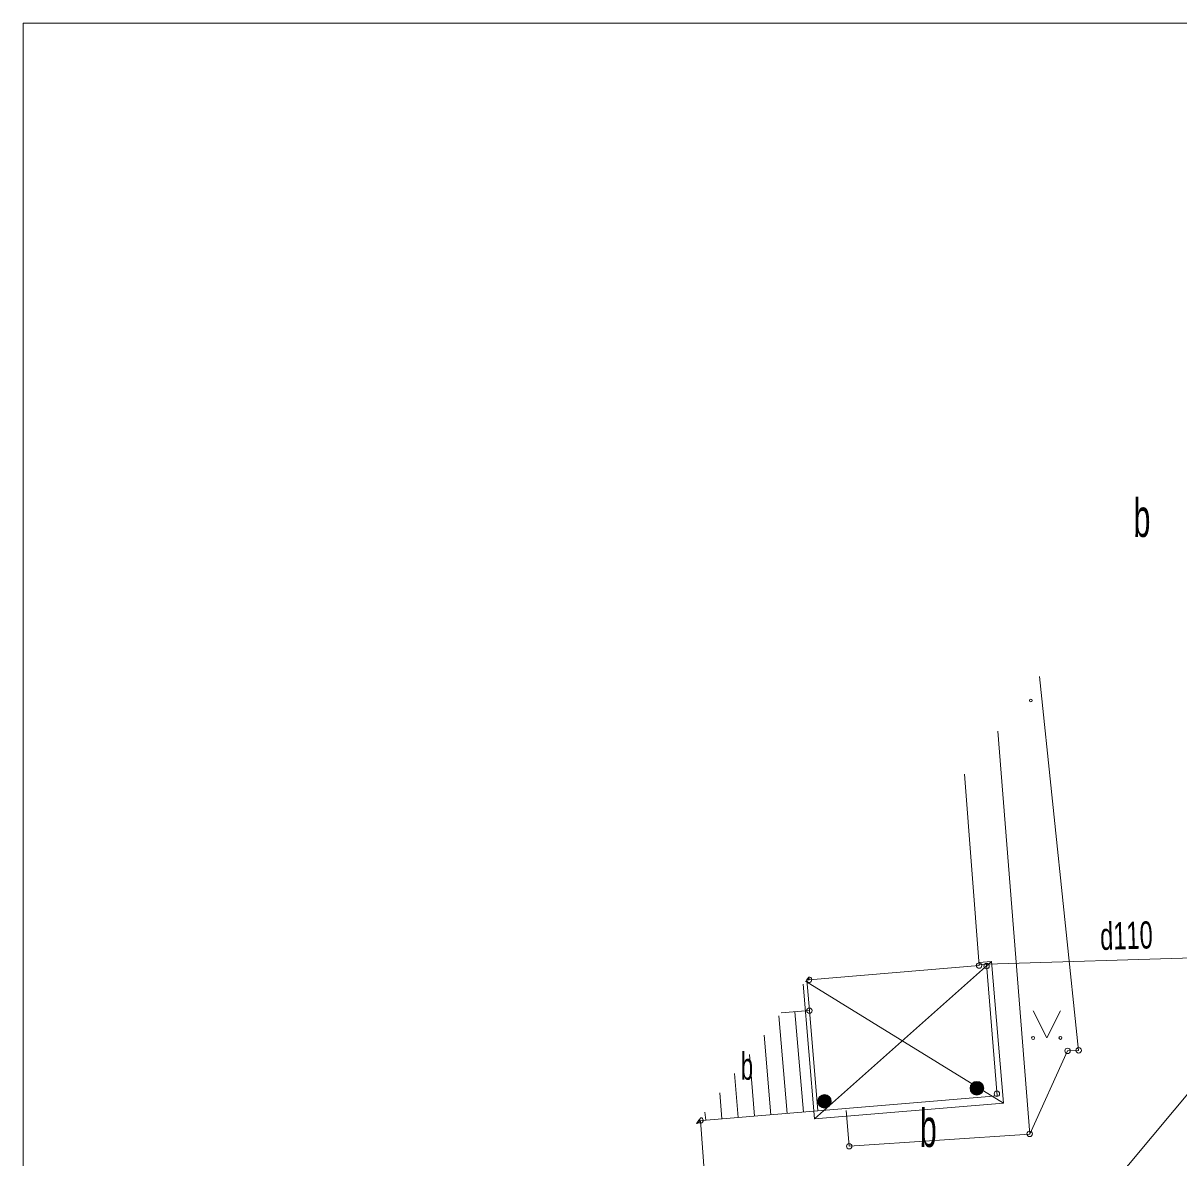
# Model space of a CAD drawing. Extents: x -1271.1 to -1218.8, y 769 to 838.3.
# Drawn here: x -1268.85 to -1247.62, y 817.43 to 838.28 of the extents above; entities that cross this region are included whole.
import ezdxf
from ezdxf.enums import TextEntityAlignment as Align

# ---------------------------------------------------------------- set-up
doc = ezdxf.new("R2010")
doc.units = 0
doc.header["$LTSCALE"] = 0.2
for name, color, linetype, lineweight in [('1', 7, 'Continuous', 13), ('19', 7, 'Continuous', 13), ('3', 7, 'Continuous', 13), ('5', 7, 'Continuous', 13), ('56', 7, 'Continuous', 13), ('59', 7, 'Continuous', 13), ('6', 7, 'Continuous', 13), ('60', 7, 'Continuous', 13), ('63', 7, 'Continuous', 13), ('7', 7, 'Continuous', 13)]:
    doc.layers.add(name, color=color, linetype=linetype, lineweight=lineweight)
for name, color, linetype in [('10', 7, 'Continuous'), ('11', 7, 'Continuous'), ('15', 7, 'Continuous')]:
    doc.layers.add(name, color=color, linetype=linetype)

msp = doc.modelspace()

# ---------------------------------------------------------------- hatches: boundary and pattern name
at = {"layer": '7'}
for points in [[(-1251.21, 818.7142, 1), (-1251.46, 818.7142, 1)], [(-1254.01, 818.4732, 1), (-1254.26, 818.4732, 1)]]:
    msp.add_hatch(color=256, dxfattribs=at).paths.add_polyline_path(points)

# ---------------------------------------------------------------- linework, layer by layer
at = {"layer": '1'}
msp.add_spline([(-1235.8, 825.801), (-1237.913, 825.174), (-1239.203, 823.346), (-1241.709, 821.268), (-1246.557, 815.58), (-1256.526, 805.053), (-1260.592, 799.147), (-1261.416, 795.29), (-1262.742, 791.444), (-1262.206, 785.139)], degree=3, dxfattribs=at)
at = {"layer": '19'}
msp.add_spline([(-1253.457, 785.393), (-1253.726, 794.104), (-1251.637, 801.373), (-1250.122, 804.26), (-1247.608, 807.348), (-1239.437, 815.545), (-1236.508, 819.221), (-1228.799, 821.851), (-1223.357, 826.161), (-1220.079, 827.95)], degree=3, dxfattribs=at)
at = {"layer": '3'}
msp.add_line((-1251.16, 820.99), (-1241.778, 821.284), dxfattribs=at)
at = {"layer": '5'}
msp.add_lwpolyline([(-1250.301, 820.138), (-1250.051, 819.638), (-1249.801, 820.138)], dxfattribs=at)
for centre, radius in [((-1250.345, 825.8366), 0.0263), ((-1250.3016, 819.6377), 0.028), ((-1249.8016, 819.6377), 0.0263)]:
    msp.add_circle(centre, radius, dxfattribs=at)
at = {"layer": '56'}
for p, q in [((-1251.294, 820.98), (-1251.16, 820.99)), ((-1251.16, 820.99), (-1250.965, 818.572)), ((-1254.418, 820.706), (-1254.458, 820.703)), ((-1254.458, 820.703), (-1254.411, 820.139)), ((-1254.93, 820.096), (-1254.411, 820.139)), ((-1254.676, 820.117), (-1254.522, 818.275)), ((-1254.411, 820.139), (-1254.257, 818.297)), ((-1254.971, 820.042), (-1254.821, 818.25)), ((-1255.242, 819.689), (-1255.12, 818.225)), ((-1255.514, 819.335), (-1255.419, 818.2)), ((-1255.786, 818.982), (-1255.718, 818.175)), ((-1256.057, 818.628), (-1256.017, 818.15)), ((-1256.452, 818.114), (-1250.965, 818.572)), ((-1256.329, 818.275), (-1256.316, 818.125))]:
    msp.add_line(p, q, dxfattribs=at)
at = {"layer": '59'}
for p, q in [((-1251.56, 824.483), (-1251.293, 820.967)), ((-1254.418, 820.706), (-1251.293, 820.967)), ((-1254.422, 820.757), (-1254.418, 820.706))]:
    msp.add_line(p, q, dxfattribs=at)
at = {"layer": '6'}
for p, q in [((-1254.423, 820.756), (-1254.467, 820.698)), ((-1256.431, 818.142), (-1256.487, 818.069)), ((-1256.407, 818.173), (-1256.459, 818.105))]:
    msp.add_line(p, q, dxfattribs=at)
for centre in [(-1251.293, 820.9672), (-1251.157, 820.9562), (-1254.411, 820.1392), (-1249.669, 819.3992), (-1249.466, 819.4092), (-1250.968, 818.6122), (-1250.365, 817.8762), (-1253.68, 817.6481)]:
    msp.add_circle(centre, 0.05, dxfattribs=at)
for centre, start, end in [((-1254.418, 820.7062), 189.39039, 95.55119), ((-1256.474, 818.1172), 255.07057, 29.871), ((-1256.412, 818.1232), 200.73646, 84.20513)]:
    msp.add_arc(centre, 0.05, start, end, dxfattribs=at)
at = {"layer": '60'}
for p, q in [((-1254.318, 818.152), (-1251.065, 821.041)), ((-1251.297, 821.023), (-1251.065, 821.041)), ((-1251.065, 821.041), (-1250.848, 818.442)), ((-1254.525, 820.623), (-1254.318, 818.152)), ((-1254.481, 820.681), (-1250.848, 818.442)), ((-1254.419, 820.721), (-1254.452, 820.719)), ((-1254.318, 818.152), (-1250.848, 818.442))]:
    msp.add_line(p, q, dxfattribs=at)
at = {"layer": '63'}
for p, q in [((-1250.952, 825.274), (-1250.362, 817.869)), ((-1250.362, 817.869), (-1249.669, 819.399)), ((-1253.68, 817.648), (-1253.735, 818.308)), ((-1253.68, 817.648), (-1250.362, 817.869))]:
    msp.add_line(p, q, dxfattribs=at)
for points in [[(-1218.845, 838.277), (-1268.854, 838.277), (-1268.854, 768.981)], [(-1256.412, 818.123), (-1256.201, 815.29), (-1252.408, 813.098), (-1251.504, 813.774), (-1247.278, 818.829), (-1247.088, 823.447), (-1246.858, 826.564), (-1246.095, 828.381), (-1245.357, 829.125), (-1242.02, 832.546), (-1243.096, 833.394)], [(-1249.669, 819.399), (-1249.466, 819.409), (-1250.183, 826.276)]]:
    msp.add_lwpolyline(points, dxfattribs=at)
at = {"layer": '7'}
for centre in [(-1251.335, 818.7142), (-1254.135, 818.4732)]:
    msp.add_circle(centre, 0.125, dxfattribs=at)

# ---------------------------------------------------------------- texts
at = {"layer": '10', "width": 0.6}
for p in [(-1248.3025, 828.84), (-1252.2275, 817.635)]:
    msp.add_text('b', height=0.7, dxfattribs=at).set_placement(p, align=Align.CENTER)
at = {"layer": '11', "width": 0.65}
msp.add_text('d110', height=0.5, rotation=1.795, dxfattribs=at).set_placement((-1248.5808, 821.268), align=Align.CENTER)
at = {"layer": '15', "width": 0.6}
msp.add_text('b', height=0.5, dxfattribs=at).set_placement((-1255.669, 818.869))

doc.saveas('drawing.dxf')
